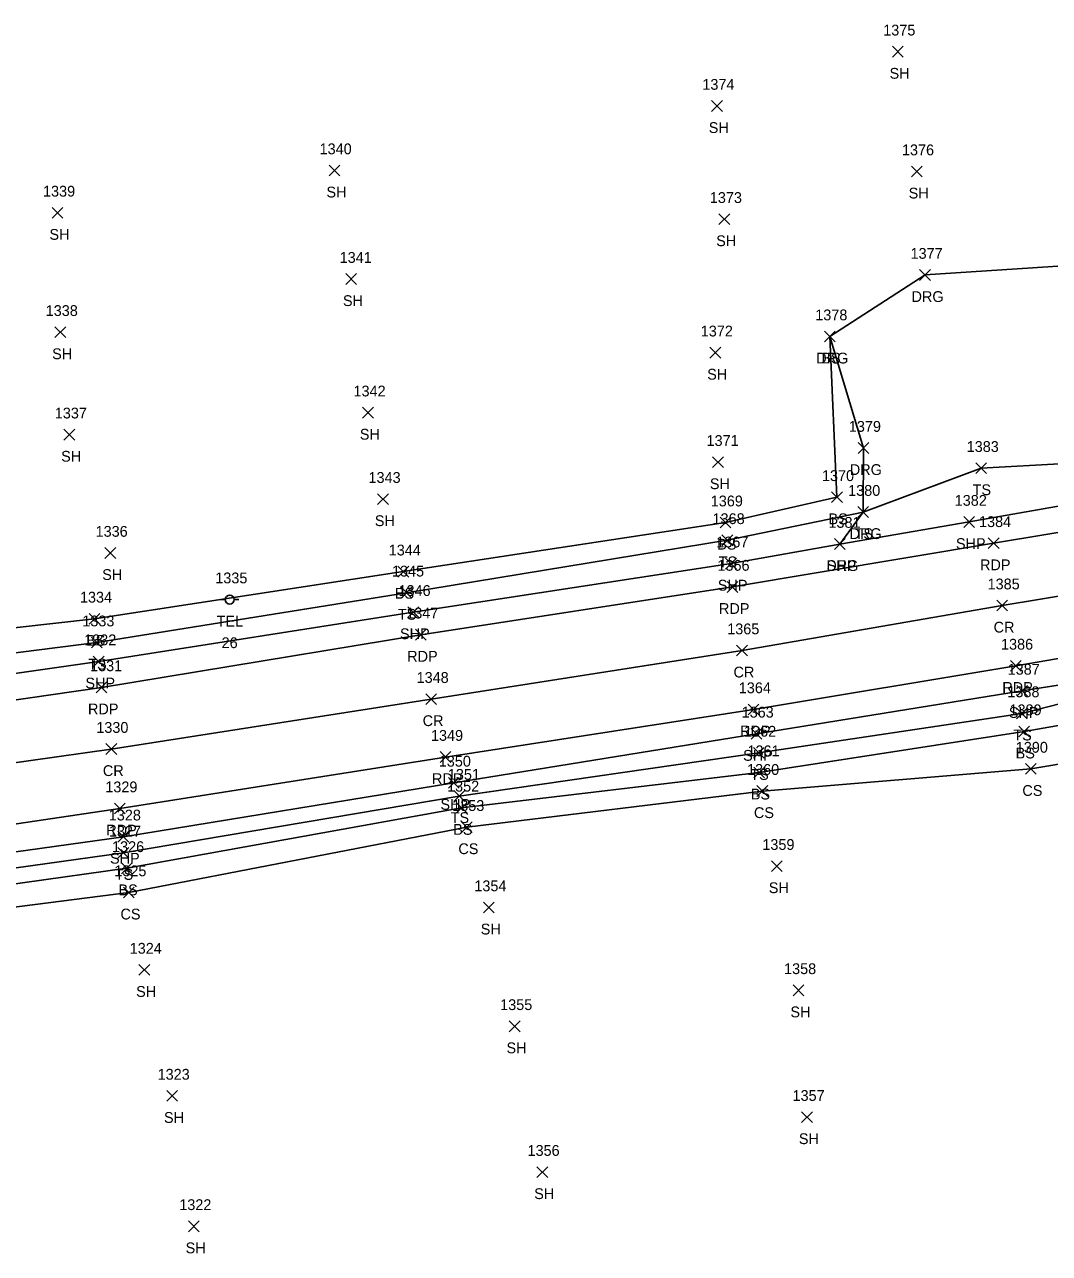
# Model space of a CAD drawing. Extents: x 1497084 to 1499861, y 734741 to 735567.
# Drawn here: x 1498658.8 to 1498848.7, y 735264.4 to 735492 of the extents above; entities that cross this region are included whole.
import ezdxf

# ---------------------------------------------------------------- set-up
doc = ezdxf.new("R2010")
doc.units = 0
for name, color, linetype in [('L_A', 7, 'Continuous'), ('L_I', 7, 'Continuous'), ('L_TIC', 7, 'Continuous'), ('LELB', 7, 'Continuous'), ('P_A', 7, 'Continuous'), ('P_I', 7, 'Continuous'), ('P_TIC', 7, 'Continuous'), ('PET', 7, 'Continuous'), ('PRC', 7, 'Continuous'), ('PSP', 7, 'Continuous'), ('R_A', 7, 'Continuous'), ('R_I', 7, 'Continuous'), ('R_TIC', 7, 'Continuous'), ('RDG', 7, 'Continuous'), ('U_A', 7, 'Continuous'), ('U_C', 7, 'Continuous'), ('U_I', 7, 'Continuous'), ('UP', 7, 'Continuous')]:
    doc.layers.add(name, color=color, linetype=linetype)

msp = doc.modelspace()

# ---------------------------------------------------------------- linework, layer by layer
at = {"layer": 'L_TIC'}
for points in [[(1498819.56, 735485.94), (1498821.56, 735487.94)], [(1498821.56, 735485.94), (1498819.56, 735487.94)], [(1498786.07, 735475.89), (1498788.07, 735477.89)], [(1498788.07, 735475.89), (1498786.07, 735477.89)], [(1498715.24, 735463.95), (1498717.24, 735465.95)], [(1498717.24, 735463.95), (1498715.24, 735465.95)], [(1498823.09, 735463.76), (1498825.09, 735465.76)], [(1498825.09, 735463.76), (1498823.09, 735465.76)], [(1498663.93, 735456.11), (1498665.93, 735458.11)], [(1498665.93, 735456.11), (1498663.93, 735458.11)], [(1498787.44, 735454.93), (1498789.44, 735456.93)], [(1498789.44, 735454.93), (1498787.44, 735456.93)], [(1498718.3, 735443.84), (1498720.3, 735445.84)], [(1498720.3, 735443.84), (1498718.3, 735445.84)], [(1498664.43, 735434), (1498666.43, 735436)], [(1498666.43, 735434), (1498664.43, 735436)], [(1498806.97, 735433.2), (1498808.97, 735435.2)], [(1498808.97, 735433.2), (1498806.97, 735435.2)], [(1498785.77, 735430.21), (1498787.77, 735432.21)], [(1498787.77, 735430.21), (1498785.77, 735432.21)], [(1498721.43, 735419.1), (1498723.43, 735421.1)], [(1498723.43, 735419.1), (1498721.43, 735421.1)], [(1498666.1, 735415.02), (1498668.1, 735417.02)], [(1498668.1, 735415.02), (1498666.1, 735417.02)], [(1498786.27, 735409.93), (1498788.27, 735411.93)], [(1498788.27, 735409.93), (1498786.27, 735411.93)], [(1498835.02, 735408.82), (1498837.02, 735410.82)], [(1498837.02, 735408.82), (1498835.02, 735410.82)], [(1498724.21, 735403.09), (1498726.21, 735405.09)], [(1498726.21, 735403.09), (1498724.21, 735405.09)], [(1498808.3, 735403.43), (1498810.3, 735405.43)], [(1498810.3, 735403.43), (1498808.3, 735405.43)], [(1498787.67, 735398.74), (1498789.67, 735400.74)], [(1498789.67, 735398.74), (1498787.67, 735400.74)], [(1498813.15, 735400.69), (1498815.15, 735402.69)], [(1498815.15, 735400.69), (1498813.15, 735402.69)], [(1498787.99, 735395.46), (1498789.99, 735397.46)], [(1498789.99, 735395.46), (1498787.99, 735397.46)], [(1498673.71, 735393.11), (1498675.71, 735395.11)], [(1498675.71, 735393.11), (1498673.71, 735395.11)], [(1498727.97, 735389.65), (1498729.97, 735391.65)], [(1498729.97, 735389.65), (1498727.97, 735391.65)], [(1498728.57, 735385.75), (1498730.57, 735387.75)], [(1498730.57, 735385.75), (1498728.57, 735387.75)], [(1498670.76, 735380.92), (1498672.76, 735382.92)], [(1498672.76, 735380.92), (1498670.76, 735382.92)], [(1498671.2, 735376.52), (1498673.2, 735378.52)], [(1498673.2, 735376.52), (1498671.2, 735378.52)], [(1498842.56, 735363.4), (1498844.56, 735365.4)], [(1498844.56, 735363.4), (1498842.56, 735365.4)], [(1498842.96, 735360.06), (1498844.96, 735362.06)], [(1498844.96, 735360.06), (1498842.96, 735362.06)], [(1498793.83, 735356.09), (1498795.83, 735358.09)], [(1498795.83, 735356.09), (1498793.83, 735358.09)], [(1498844.2, 735353.12), (1498846.2, 735355.12)], [(1498846.2, 735353.12), (1498844.2, 735355.12)], [(1498793.9, 735352.46), (1498795.9, 735354.46)], [(1498795.9, 735352.46), (1498793.9, 735354.46)], [(1498794.48, 735349.02), (1498796.48, 735351.02)], [(1498796.48, 735349.02), (1498794.48, 735351.02)], [(1498738.34, 735348.1), (1498740.34, 735350.1)], [(1498740.34, 735348.1), (1498738.34, 735350.1)], [(1498738.77, 735345.92), (1498740.77, 735347.92)], [(1498740.77, 735345.92), (1498738.77, 735347.92)], [(1498739.72, 735342.34), (1498741.72, 735344.34)], [(1498741.72, 735342.34), (1498739.72, 735344.34)], [(1498676.12, 735337.58), (1498678.12, 735339.58)], [(1498678.12, 735337.58), (1498676.12, 735339.58)], [(1498797.18, 735335.12), (1498799.18, 735337.12)], [(1498799.18, 735335.12), (1498797.18, 735337.12)], [(1498676.77, 735334.72), (1498678.77, 735336.72)], [(1498678.77, 735334.72), (1498676.77, 735336.72)], [(1498677.14, 735330.24), (1498679.14, 735332.24)], [(1498679.14, 735330.24), (1498677.14, 735332.24)], [(1498743.82, 735327.46), (1498745.82, 735329.46)], [(1498745.82, 735327.46), (1498743.82, 735329.46)], [(1498679.99, 735315.9), (1498681.99, 735317.9)], [(1498681.99, 735315.9), (1498679.99, 735317.9)], [(1498801.19, 735312.12), (1498803.19, 735314.12)], [(1498803.19, 735312.12), (1498801.19, 735314.12)], [(1498748.61, 735305.46), (1498750.61, 735307.46)], [(1498750.61, 735305.46), (1498748.61, 735307.46)], [(1498685.15, 735292.57), (1498687.15, 735294.57)], [(1498687.15, 735292.57), (1498685.15, 735294.57)], [(1498802.76, 735288.64), (1498804.76, 735290.64)], [(1498804.76, 735288.64), (1498802.76, 735290.64)], [(1498753.73, 735278.46), (1498755.73, 735280.46)], [(1498755.73, 735278.46), (1498753.73, 735280.46)], [(1498689.17, 735268.42), (1498691.17, 735270.42)], [(1498691.17, 735268.42), (1498689.17, 735270.42)]]:
    msp.add_lwpolyline(points, dxfattribs=at)
at = {"layer": 'LELB'}
for points in [[(1498337.56, 735327.03), (1498345.07, 735328.8), (1498360.02, 735336.05), (1498371.93, 735339.18), (1498383.26, 735341.12), (1498406.51, 735345.51), (1498447.67, 735353.97), (1498496.97, 735359.09), (1498555.39, 735373.27), (1498586.79, 735381.8), (1498595.75, 735372.64), (1498613.85, 735375.41), (1498671.76, 735381.92), (1498728.97, 735390.65), (1498788.67, 735399.74), (1498809.3, 735404.43), (1498807.97, 735434.2)], [(1498337.34, 735322.86), (1498344.97, 735324.75), (1498384.58, 735334.28), (1498409.2, 735337.4), (1498355.01, 735326.99), (1498382.45, 735331.79), (1498397.41, 735335.39), (1498428.62, 735342.29), (1498447.37, 735348.53), (1498497.98, 735350.74), (1498557.57, 735362.02), (1498577.34, 735369.5), (1498587.41, 735365.45), (1498611.95, 735369.89), (1498672.2, 735377.52), (1498729.57, 735386.75), (1498788.99, 735396.46), (1498814.15, 735401.69), (1498836.02, 735409.82), (1498851.62, 735410.69)], [(1498435.91, 735287.74), (1498479.86, 735295.91), (1498506.16, 735305.79), (1498562.09, 735310.28), (1498620.2, 735323.83), (1498678.14, 735331.24), (1498740.72, 735343.34), (1498795.48, 735350.02), (1498845.2, 735354.12), (1498873.2, 735358.8), (1498904.58, 735361.51), (1498941.92, 735355.1), (1499002.35, 735368.44), (1499018.4, 735380.28), (1499017.69, 735389.23)], [(1498348.47, 735290.66), (1498349.3, 735292.12), (1498356.63, 735290), (1498367.4, 735288.15), (1498383.02, 735293.44), (1498402.41, 735293.85), (1498412.25, 735297.62), (1498434.81, 735303.59), (1498479.54, 735310.53), (1498504.67, 735314.81), (1498560.97, 735322.47), (1498619.67, 735330.56), (1498677.12, 735338.58), (1498739.34, 735349.1), (1498794.83, 735357.09), (1498843.56, 735364.4), (1498863.08, 735369.39)], [(1498347.81, 735289.73), (1498349.19, 735291.09), (1498355.19, 735287.19), (1498360.89, 735284.04), (1498368.96, 735282.7), (1498386.86, 735285.14), (1498402.12, 735288.93), (1498434.54, 735297.05), (1498479.17, 735305.56), (1498505.43, 735311.83), (1498561.53, 735319.26), (1498619.71, 735327.6), (1498677.77, 735335.72), (1498739.77, 735346.92), (1498794.9, 735353.46), (1498843.96, 735361.06), (1498867.57, 735365.18)]]:
    msp.add_lwpolyline(points, dxfattribs=at)
at = {"layer": 'P_TIC'}
for points in [[(1498832.8, 735398.85), (1498834.8, 735400.85)], [(1498834.8, 735398.85), (1498832.8, 735400.85)], [(1498808.84, 735394.77), (1498810.84, 735396.77)], [(1498810.84, 735394.77), (1498808.84, 735396.77)], [(1498837.32, 735394.91), (1498839.32, 735396.91)], [(1498839.32, 735394.91), (1498837.32, 735396.91)], [(1498788.68, 735391.14), (1498790.68, 735393.14)], [(1498790.68, 735391.14), (1498788.68, 735393.14)], [(1498788.96, 735386.82), (1498790.96, 735388.82)], [(1498790.96, 735386.82), (1498788.96, 735388.82)], [(1498838.89, 735383.37), (1498840.89, 735385.37)], [(1498840.89, 735383.37), (1498838.89, 735385.37)], [(1498729.82, 735382.15), (1498731.82, 735384.15)], [(1498731.82, 735382.15), (1498729.82, 735384.15)], [(1498731.2, 735377.98), (1498733.2, 735379.98)], [(1498733.2, 735377.98), (1498731.2, 735379.98)], [(1498790.71, 735375.05), (1498792.71, 735377.05)], [(1498792.71, 735375.05), (1498790.71, 735377.05)], [(1498671.54, 735373.02), (1498673.54, 735375.02)], [(1498673.54, 735373.02), (1498671.54, 735375.02)], [(1498841.44, 735372.21), (1498843.44, 735374.21)], [(1498843.44, 735372.21), (1498841.44, 735374.21)], [(1498672.07, 735368.22), (1498674.07, 735370.22)], [(1498674.07, 735368.22), (1498672.07, 735370.22)], [(1498842.61, 735367.57), (1498844.61, 735369.57)], [(1498844.61, 735367.57), (1498842.61, 735369.57)], [(1498733.12, 735366.05), (1498735.12, 735368.05)], [(1498735.12, 735366.05), (1498733.12, 735368.05)], [(1498792.85, 735364.14), (1498794.85, 735366.14)], [(1498794.85, 735364.14), (1498792.85, 735366.14)], [(1498793.38, 735359.63), (1498795.38, 735361.63)], [(1498795.38, 735359.63), (1498793.38, 735361.63)], [(1498673.88, 735356.8), (1498675.88, 735358.8)], [(1498675.88, 735356.8), (1498673.88, 735358.8)], [(1498735.79, 735355.32), (1498737.79, 735357.32)], [(1498737.79, 735355.32), (1498735.79, 735357.32)], [(1498737.32, 735350.55), (1498739.32, 735352.55)], [(1498739.32, 735350.55), (1498737.32, 735352.55)], [(1498675.47, 735345.79), (1498677.47, 735347.79)], [(1498677.47, 735345.79), (1498675.47, 735347.79)], [(1498676.11, 735340.57), (1498678.11, 735342.57)], [(1498678.11, 735340.57), (1498676.11, 735342.57)]]:
    msp.add_lwpolyline(points, dxfattribs=at)
at = {"layer": 'PET'}
for points in [[(1498338.16, 735318.88), (1498357.92, 735321.69), (1498398.8, 735327.5), (1498451.3, 735335.22), (1498500.84, 735343.24), (1498558.12, 735351.59), (1498613.71, 735360.6), (1498673.07, 735369.22), (1498732.2, 735378.98), (1498789.96, 735387.82), (1498838.32, 735395.91), (1498888.99, 735404.3)], [(1498338.16, 735318.88), (1498339.87, 735308.1), (1498341.54, 735297.2), (1498360.21, 735300.18), (1498403.13, 735306.7), (1498454.97, 735313.53), (1498504.37, 735320.92), (1498560.62, 735329.11), (1498618.15, 735338.15), (1498676.47, 735346.79), (1498736.79, 735356.32), (1498793.85, 735365.14), (1498842.44, 735373.21), (1498892.67, 735381.87)]]:
    msp.add_lwpolyline(points, dxfattribs=at)
at = {"layer": 'PRC'}
msp.add_lwpolyline([(1498339.87, 735308.1), (1498359.7, 735310.92), (1498400.74, 735317.79), (1498454.01, 735324.13), (1498502.48, 735331.98), (1498559.28, 735340.31), (1498615.27, 735349.36), (1498674.88, 735357.8), (1498734.12, 735367.05), (1498791.71, 735376.05), (1498839.89, 735384.37), (1498890.74, 735392.79)], dxfattribs=at)
at = {"layer": 'PSP'}
for points in [[(1498357.92, 735321.69), (1498398.08, 735329.19), (1498452.34, 735339.17), (1498499.61, 735346.69), (1498557.87, 735356.09), (1498612.39, 735365.43), (1498672.54, 735374.02), (1498730.82, 735383.15), (1498789.68, 735392.14), (1498809.84, 735395.77), (1498833.8, 735399.85), (1498855.6, 735403.69)], [(1498360.21, 735300.18), (1498403.51, 735303.5), (1498455.72, 735308.98), (1498504.77, 735316.34), (1498560.61, 735324.72), (1498619.04, 735333.45), (1498677.11, 735341.57), (1498738.32, 735351.55), (1498794.38, 735360.63), (1498843.61, 735368.57), (1498860.46, 735371.23)]]:
    msp.add_lwpolyline(points, dxfattribs=at)
at = {"layer": 'R_TIC'}
for points in [[(1498824.62, 735444.59), (1498826.62, 735446.59)], [(1498826.62, 735444.59), (1498824.62, 735446.59)], [(1498824.62, 735444.59), (1498826.62, 735446.59)], [(1498826.62, 735444.59), (1498824.62, 735446.59)], [(1498806.97, 735433.2), (1498808.97, 735435.2)], [(1498808.97, 735433.2), (1498806.97, 735435.2)], [(1498813.2, 735412.55), (1498815.2, 735414.55)], [(1498815.2, 735412.55), (1498813.2, 735414.55)], [(1498813.15, 735400.69), (1498815.15, 735402.69)], [(1498815.15, 735400.69), (1498813.15, 735402.69)], [(1498808.84, 735394.77), (1498810.84, 735396.77)], [(1498810.84, 735394.77), (1498808.84, 735396.77)]]:
    msp.add_lwpolyline(points, dxfattribs=at)
at = {"layer": 'RDG'}
for points in [[(1498825.62, 735445.59), (1498866.36, 735448.26), (1498854.82, 735428.45), (1498851.62, 735410.69), (1498855.6, 735403.69)], [(1498825.62, 735445.59), (1498807.97, 735434.2), (1498814.2, 735413.55), (1498814.15, 735401.69), (1498809.84, 735395.77)]]:
    msp.add_lwpolyline(points, dxfattribs=at)
at = {"layer": 'UP'}
for p, q in [((1498695.17, 735385.49), (1498696, 735385.49)), ((1498696.83, 735385.49), (1498696.83, 735385.49)), ((1498698.5, 735385.49), (1498697.67, 735385.49)), ((1498697.67, 735385.49), (1498697.67, 735385.49)), ((1498698.5, 735385.49), (1498698.5, 735385.49))]:
    msp.add_line(p, q, dxfattribs=at)
msp.add_circle((1498696.83, 735385.49), 0.833, dxfattribs=at)

# ---------------------------------------------------------------- texts
at = {"layer": 'L_A'}
for s, p in [('SH', (1498819.05, 735481.94)), ('SH', (1498785.55, 735471.89)), ('SH', (1498714.73, 735459.95)), ('SH', (1498822.58, 735459.76)), ('SH', (1498663.42, 735452.11)), ('SH', (1498786.93, 735450.93)), ('SH', (1498717.79, 735439.84)), ('SH', (1498663.92, 735430)), ('BS', (1498806.41, 735429.2)), ('SH', (1498785.26, 735426.21)), ('SH', (1498720.92, 735415.1)), ('SH', (1498665.59, 735411.02)), ('SH', (1498785.76, 735405.93)), ('TS', (1498834.43, 735404.82)), ('SH', (1498723.7, 735399.09)), ('BS', (1498807.74, 735399.43)), ('TS', (1498812.56, 735396.69)), ('BS', (1498787.11, 735394.74)), ('TS', (1498787.4, 735391.46)), ('SH', (1498673.2, 735389.11)), ('BS', (1498727.41, 735385.65)), ('TS', (1498727.98, 735381.75)), ('BS', (1498670.2, 735376.92)), ('TS', (1498670.61, 735372.52)), ('TS', (1498841.97, 735359.4)), ('BS', (1498842.4, 735356.06)), ('TS', (1498793.24, 735352.09)), ('BS', (1498793.34, 735348.46)), ('CS', (1498843.64, 735349.12)), ('TS', (1498737.75, 735344.1)), ('CS', (1498793.92, 735345.02)), ('BS', (1498738.21, 735341.92)), ('CS', (1498739.17, 735338.34)), ('TS', (1498675.53, 735333.58)), ('BS', (1498676.21, 735330.72)), ('SH', (1498796.67, 735331.12)), ('CS', (1498676.58, 735326.24)), ('SH', (1498743.31, 735323.46)), ('SH', (1498679.47, 735311.9)), ('SH', (1498800.68, 735308.12)), ('SH', (1498748.09, 735301.46)), ('SH', (1498684.64, 735288.57)), ('SH', (1498802.25, 735284.64)), ('SH', (1498753.22, 735274.46)), ('SH', (1498688.65, 735264.42))]:
    msp.add_text(s, height=2, dxfattribs=at).set_placement(p)
at = {"layer": 'L_I'}
for s, p in [('1375', (1498817.87, 735489.94)), ('1374', (1498784.37, 735479.89)), ('1340', (1498713.46, 735467.95)), ('1376', (1498821.34, 735467.76)), ('1339', (1498662.23, 735460.11)), ('1373', (1498785.75, 735458.93)), ('1341', (1498717.18, 735447.84)), ('1338', (1498662.73, 735438)), ('1378', (1498805.28, 735437.2)), ('1372', (1498784.07, 735434.21)), ('1342', (1498719.74, 735423.1)), ('1337', (1498664.41, 735419.02)), ('1371', (1498785.14, 735413.93)), ('1383', (1498833.33, 735412.82)), ('1343', (1498722.52, 735407.09)), ('1370', (1498806.52, 735407.43)), ('1380', (1498811.37, 735404.69)), ('1369', (1498785.92, 735402.74)), ('1368', (1498786.25, 735399.46)), ('1336', (1498671.97, 735397.11)), ('1344', (1498726.27, 735393.65)), ('1345', (1498726.87, 735389.75)), ('1334', (1498669.07, 735384.92)), ('1333', (1498669.51, 735380.52)), ('1388', (1498840.87, 735367.4)), ('1389', (1498841.26, 735364.06)), ('1362', (1498792.09, 735360.09)), ('1361', (1498792.72, 735356.46)), ('1390', (1498842.42, 735357.12)), ('1360', (1498792.65, 735353.02)), ('1351', (1498737.22, 735352.1)), ('1352', (1498737.08, 735349.92)), ('1353', (1498738.03, 735346.34)), ('1327', (1498674.43, 735341.58)), ('1326', (1498675.02, 735338.72)), ('1359', (1498795.48, 735339.12)), ('1325', (1498675.44, 735334.24)), ('1354', (1498742.13, 735331.46)), ('1324', (1498678.29, 735319.9)), ('1358', (1498799.5, 735316.12)), ('1355', (1498746.91, 735309.46)), ('1323', (1498683.46, 735296.57)), ('1357', (1498801.07, 735292.64)), ('1356', (1498751.98, 735282.46)), ('1322', (1498687.47, 735272.42))]:
    msp.add_text(s, height=2, dxfattribs=at).set_placement(p)
at = {"layer": 'P_A'}
for s, p in [('SHP', (1498831.34, 735394.85)), ('SHP', (1498807.38, 735390.77)), ('RDP', (1498835.8, 735390.91)), ('SHP', (1498787.22, 735387.14)), ('RDP', (1498787.44, 735382.82)), ('SHP', (1498728.36, 735378.15)), ('CR', (1498838.32, 735379.37)), ('RDP', (1498729.69, 735373.98)), ('SHP', (1498670.08, 735369.02)), ('CR', (1498790.14, 735371.05)), ('RDP', (1498839.93, 735368.21)), ('RDP', (1498670.56, 735364.22)), ('SHP', (1498841.14, 735363.57)), ('CR', (1498732.56, 735362.05)), ('RDP', (1498791.34, 735360.14)), ('SHP', (1498791.91, 735355.63)), ('CR', (1498673.32, 735352.8)), ('RDP', (1498734.28, 735351.32)), ('SHP', (1498735.85, 735346.55)), ('RDP', (1498673.95, 735341.79)), ('SHP', (1498674.64, 735336.57))]:
    msp.add_text(s, height=2, dxfattribs=at).set_placement(p)
at = {"layer": 'P_I'}
for s, p in [('1382', (1498831.11, 735402.85)), ('1381', (1498807.72, 735398.77)), ('1384', (1498835.62, 735398.91)), ('1367', (1498786.94, 735395.14)), ('1366', (1498787.16, 735390.82)), ('1385', (1498837.2, 735387.37)), ('1346', (1498728.08, 735386.15)), ('1347', (1498729.51, 735381.98)), ('1365', (1498788.97, 735379.05)), ('1332', (1498669.85, 735377.02)), ('1386', (1498839.69, 735376.21)), ('1331', (1498670.95, 735372.22)), ('1387', (1498840.92, 735371.57)), ('1348', (1498731.43, 735370.05)), ('1364', (1498791.11, 735368.14)), ('1363', (1498791.64, 735363.63)), ('1330', (1498672.1, 735360.8)), ('1349', (1498734.09, 735359.32)), ('1350', (1498735.54, 735354.55)), ('1329', (1498673.77, 735349.79)), ('1328', (1498674.41, 735344.57))]:
    msp.add_text(s, height=2, dxfattribs=at).set_placement(p)
at = {"layer": 'R_A'}
for p in [(1498823.11, 735440.59), (1498823.11, 735440.59), (1498805.46, 735429.2), (1498811.68, 735408.55), (1498811.64, 735396.69), (1498807.33, 735390.77)]:
    msp.add_text('DRG', height=2, dxfattribs=at).set_placement(p)
at = {"layer": 'R_I'}
for s, p in [('1377', (1498822.93, 735448.59)), ('1377', (1498822.93, 735448.59)), ('1378', (1498805.28, 735437.2)), ('1379', (1498811.5, 735416.55)), ('1380', (1498811.37, 735404.69)), ('1381', (1498807.72, 735398.77))]:
    msp.add_text(s, height=2, dxfattribs=at).set_placement(p)
at = {"layer": 'U_A'}
msp.add_text('TEL', height=2, dxfattribs=at).set_placement((1498694.39, 735380.49))
at = {"layer": 'U_C'}
msp.add_text('26', height=2, dxfattribs=at).set_placement((1498695.31, 735376.49))
at = {"layer": 'U_I'}
msp.add_text('1335', height=2, dxfattribs=at).set_placement((1498694.14, 735388.49))

doc.saveas('drawing.dxf')
